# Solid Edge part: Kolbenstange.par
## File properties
Username: ahadarics
Dokumentum tartalom típus: 0
Author: ahadarics
Last saved by: ahadarics
Revision: 79
Sűrűség: 0,000 kg/m^3
Pontosság: 0,990
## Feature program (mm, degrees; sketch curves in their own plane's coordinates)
base feature "unnamed BaseFeature 1"
sketch for "unnamed Protrusion 1" plane through (59.95, 0, 0) normal (1, 0, 0) x-axis (0, -1, 0)
  circle centre (0, 0) radius 10
extrude "unnamed Protrusion 1" add finite 32 along -normal
thread "Menet_1"  ThreadDepth = 20 mm
chamfer "Letörés_1" setback 0.7
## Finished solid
Body 1: solid body, 13 faces, 23 edges, 12 vertices.
  Faces by surface: plane 9, cylinder 3, cone 1
  Edges by curve: line 12, circle 11
Bounding box of the edges (mm): 118.500 x 20.000 x 20.000, from (-58.55, -10, -10) to (59.95, 10, 10).
Cylindrical faces by radius (mm): R4 x2, R10 x1
Conical faces (half-angle, radius in mm at the cone's reference point): 45 deg R3.3 x1
Planar faces by outward normal: +x 3, +z 1, -x 4, -z 1
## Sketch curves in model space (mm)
circle centre (59.95, 0, 0) radius 10
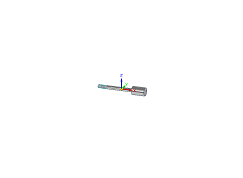
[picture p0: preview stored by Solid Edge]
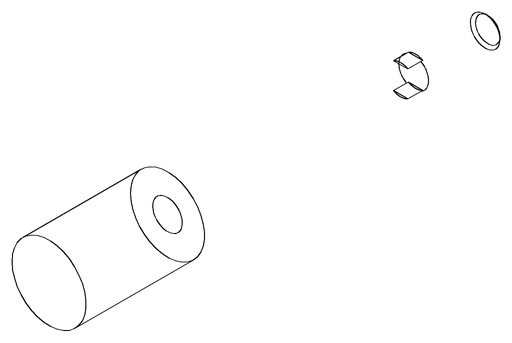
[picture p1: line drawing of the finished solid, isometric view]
